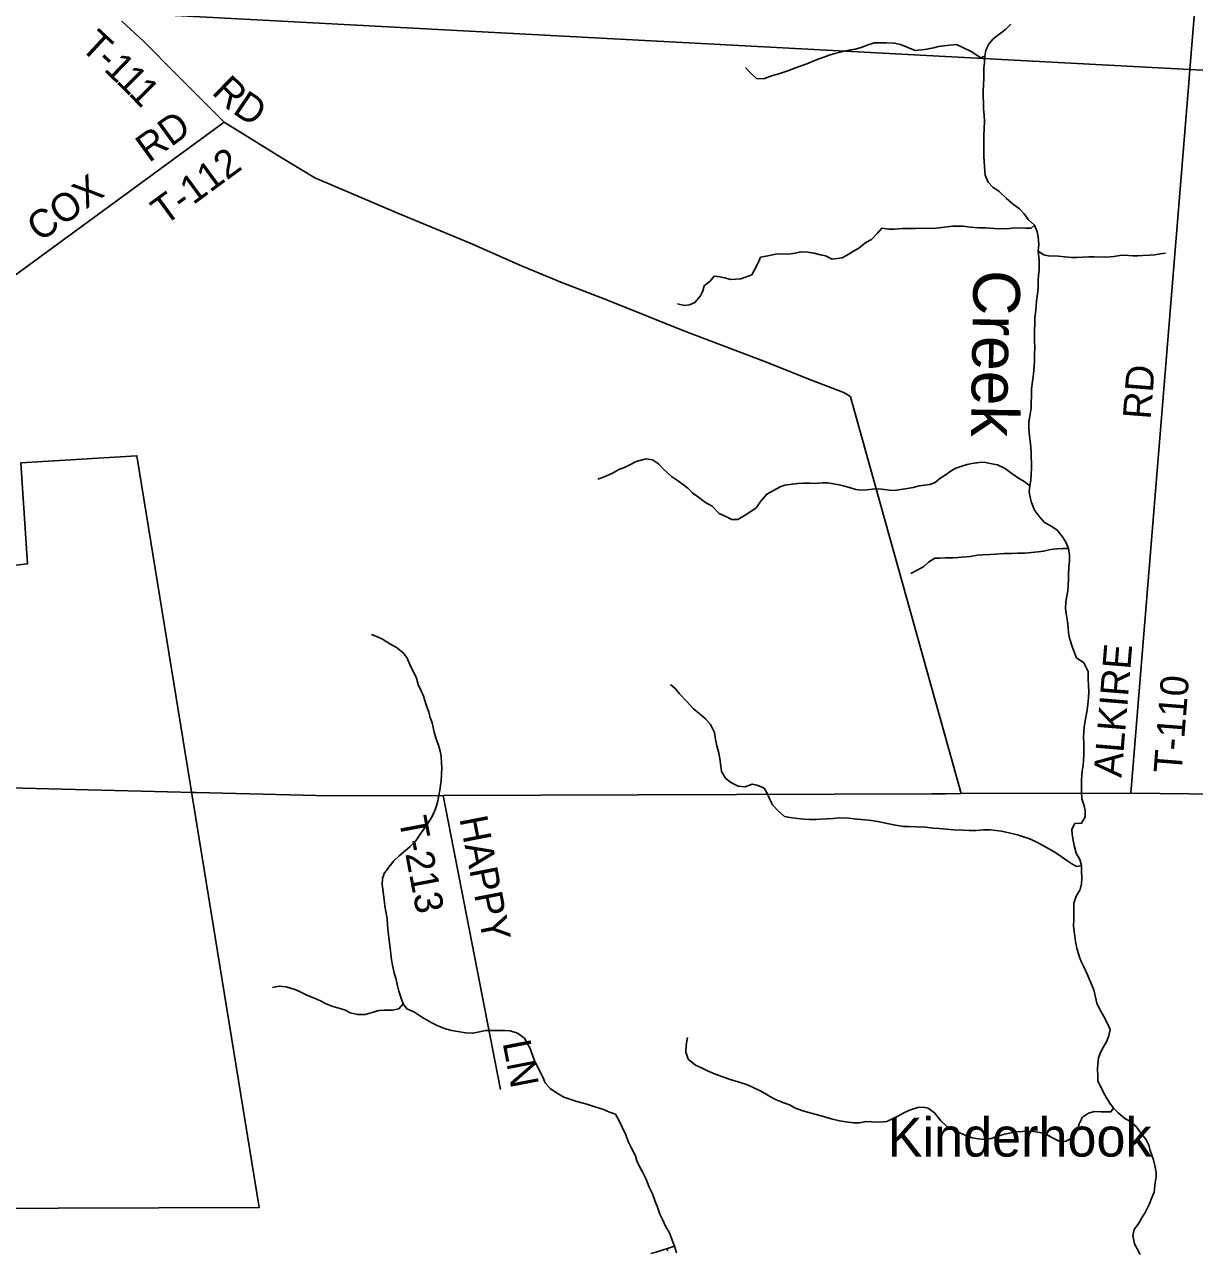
# Model space of a CAD drawing. Extents: x 1643459 to 2064572, y 425441 to 780708.
# Drawn here: x 1795345 to 1807853, y 573105 to 586239 of the extents above; entities that cross this region are included whole.
import ezdxf

# ---------------------------------------------------------------- set-up
doc = ezdxf.new("R2010")
doc.units = 0
for name, color, linetype in [('GM_X_City_Street', 7, 'Continuous'), ('GM_X_Interchange_Ramps', 7, 'Continuous'), ('GM_X_Major_River', 7, 'Continuous'), ('GM_X_Major_River_Text', 7, 'Continuous'), ('GM_X_Rail_Line_Text', 7, 'Continuous'), ('GM_X_Township_ROW', 7, 'Continuous'), ('GM_X_US_Route', 7, 'Continuous'), ('RD_X_Wall', 7, 'Continuous')]:
    doc.layers.add(name, color=color, linetype=linetype)

msp = doc.modelspace()

# ---------------------------------------------------------------- linework, layer by layer
at = {"layer": 'GM_X_City_Street'}
for points in [[(1826247, 584864), (1815752, 585365), (1810346, 585624), (1807802, 585759), (1796284, 586370), (1794642, 586457), (1794061, 586488), (1794168, 588257), (1794631, 595981), (1795084, 602890), (1800646, 605476), (1807239, 608541), (1807901, 608849), (1810366, 609995), (1808540, 616123), (1806771, 622059), (1811221, 621850), (1814649, 621689), (1819572, 621457), (1824722, 621285)], [(1796284, 586370), (1807802, 585759), (1810346, 585624)]]:
    msp.add_lwpolyline(points, dxfattribs=at)
at = {"layer": 'GM_X_Major_River_Text'}
for points in [[(1807791, 585617), (1807791, 585617), (1807802, 585759), (1808205, 590701)], [(1796386, 586275), (1796625, 586054), (1796961, 585710), (1797480, 585194), (1798089, 584818), (1798447, 584601), (1799319, 584229), (1800109, 583900), (1800658, 583659), (1801077, 583485), (1801559, 583297), (1802394, 582964), (1803249, 582640), (1803760, 582434), (1804094, 582305), (1804136, 582287), (1804176, 582258), (1805360, 578012)], [(1807172, 578017), (1807791, 585617)], [(1797480, 585194), (1795041, 583413)], [(1799821, 577994), (1800432, 574849)]]:
    msp.add_lwpolyline(points, dxfattribs=at)
at = {"layer": 'GM_X_Rail_Line_Text'}
msp.add_lwpolyline([(1792093, 580095), (1795375, 580469), (1795306, 581550), (1796546, 581627), (1797852, 573585), (1792480, 573568)], dxfattribs=at)
at = {"layer": 'GM_X_US_Route'}
for points in [[(1806475, 579990), (1806477, 580064), (1806490, 580124), (1806500, 580182), (1806502, 580238), (1806507, 580311), (1806507, 580365), (1806510, 580431), (1806516, 580507), (1806518, 580561), (1806505, 580635), (1806477, 580702), (1806442, 580760), (1806386, 580831), (1806329, 580869), (1806251, 580914), (1806199, 580968), (1806144, 581045), (1806110, 581127), (1806095, 581183), (1806087, 581242), (1806094, 581304), (1806104, 581366), (1806111, 581492), (1806109, 581548), (1806108, 581612), (1806106, 581666), (1806102, 581717), (1806095, 581783), (1806091, 581841), (1806083, 581919), (1806082, 581989), (1806094, 582051), (1806107, 582134), (1806107, 582192), (1806112, 582266), (1806110, 582342), (1806121, 582422), (1806127, 582472), (1806140, 582574), (1806144, 582653), (1806144, 582719), (1806145, 582785), (1806143, 582857), (1806144, 582973), (1806148, 583033), (1806147, 583104), (1806153, 583156), (1806162, 583228), (1806164, 583282), (1806174, 583360), (1806181, 583422), (1806181, 583504), (1806184, 583554), (1806192, 583614), (1806194, 583669), (1806191, 583719), (1806183, 583815), (1806190, 583887), (1806182, 583969), (1806171, 584022), (1806143, 584092), (1806076, 584154), (1806034, 584213), (1805982, 584269), (1805919, 584314), (1805843, 584377), (1805766, 584453), (1805698, 584498), (1805647, 584554), (1805617, 584629), (1805608, 584721), (1805606, 584775), (1805602, 584829), (1805601, 584897), (1805601, 584970), (1805600, 585050), (1805606, 585130), (1805607, 585198), (1805603, 585272), (1805598, 585338), (1805596, 585405), (1805594, 585463), (1805595, 585525), (1805597, 585595), (1805600, 585661), (1805600, 585711), (1805602, 585775), (1805609, 585834), (1805613, 585900), (1805623, 585966), (1805654, 586030), (1805698, 586084), (1805762, 586131), (1805833, 586187), (1805889, 586243)], [(1805613, 585900), (1805569, 585882), (1805464, 585949), (1805382, 585991), (1805310, 586024), (1805238, 586020), (1805174, 586013), (1805118, 586003), (1805062, 585990), (1804992, 585974), (1804938, 585968), (1804866, 585963), (1804787, 585995), (1804711, 586026), (1804647, 586041), (1804561, 586043), (1804428, 586044), (1804366, 586022), (1804291, 585995), (1804225, 585977), (1804157, 585964), (1804095, 585950), (1804009, 585929), (1803947, 585911), (1803891, 585891), (1803819, 585866), (1803727, 585826), (1803659, 585801), (1803599, 585781), (1803507, 585744), (1803409, 585712), (1803331, 585691), (1803257, 585661), (1803175, 585658), (1803109, 585718), (1803054, 585781)], [(1806143, 584092), (1806107, 584060), (1806047, 584062), (1805927, 584063), (1805875, 584058), (1805801, 584054), (1805711, 584059), (1805620, 584065), (1805548, 584066), (1805458, 584072), (1805376, 584083), (1805270, 584084), (1805206, 584076), (1805126, 584065), (1805058, 584059), (1804946, 584060), (1804871, 584058), (1804797, 584059), (1804731, 584057), (1804645, 584052), (1804585, 584052), (1804511, 584061), (1804463, 584009), (1804400, 583941), (1804338, 583906), (1804264, 583848), (1804208, 583814), (1804152, 583779), (1804088, 583745), (1804032, 583735), (1803980, 583730), (1803908, 583764), (1803856, 583777), (1803786, 583793), (1803719, 583804), (1803641, 583808), (1803583, 583793), (1803511, 583783), (1803443, 583785), (1803379, 583784), (1803273, 583763), (1803213, 583749), (1803187, 583691), (1803154, 583623), (1803120, 583563), (1803002, 583518), (1802894, 583511), (1802842, 583527), (1802782, 583541), (1802718, 583548), (1802676, 583494), (1802612, 583444), (1802597, 583390), (1802571, 583336), (1802513, 583267), (1802455, 583241), (1802401, 583233), (1802327, 583250)], [(1806183, 583815), (1806241, 583774), (1806293, 583766), (1806399, 583761), (1806466, 583753), (1806540, 583748), (1806592, 583746), (1806656, 583752), (1806724, 583755), (1806782, 583753), (1806916, 583752), (1806990, 583757), (1807054, 583769), (1807106, 583771), (1807194, 583766), (1807246, 583766), (1807297, 583769), (1807371, 583771), (1807429, 583774), (1807485, 583786), (1807543, 583794)], [(1806094, 581304), (1806034, 581350), (1805970, 581385), (1805901, 581437), (1805823, 581492), (1805747, 581529), (1805668, 581545), (1805604, 581558), (1805550, 581554), (1805474, 581544), (1805422, 581533), (1805366, 581515), (1805302, 581494), (1805252, 581464), (1805186, 581420), (1805131, 581384), (1805081, 581341), (1805023, 581319), (1804967, 581313), (1804911, 581304), (1804847, 581286), (1804783, 581275), (1804715, 581267), (1804643, 581255), (1804591, 581258), (1804539, 581266), (1804476, 581273), (1804408, 581269), (1804348, 581263), (1804288, 581260), (1804234, 581264), (1804174, 581285), (1804110, 581301), (1804056, 581314), (1803995, 581326), (1803929, 581336), (1803877, 581337), (1803797, 581331), (1803741, 581332), (1803669, 581334), (1803611, 581331), (1803553, 581321), (1803475, 581311), (1803425, 581294), (1803353, 581254), (1803281, 581217), (1803218, 581141), (1803168, 581069), (1803110, 581029), (1803050, 580990), (1802972, 580944), (1802908, 580946), (1802850, 580973), (1802770, 581008), (1802695, 581086), (1802627, 581127), (1802568, 581171), (1802486, 581230), (1802436, 581280), (1802377, 581325), (1802325, 581363), (1802263, 581404), (1802178, 581483), (1802122, 581541), (1802057, 581584), (1801991, 581594), (1801937, 581579), (1801885, 581565), (1801815, 581529), (1801761, 581500), (1801707, 581482), (1801631, 581442), (1801536, 581399), (1801474, 581377)], [(1806505, 580635), (1806445, 580634), (1806383, 580632), (1806317, 580623), (1806239, 580605), (1806181, 580597), (1806111, 580590), (1806039, 580586), (1805961, 580585), (1805897, 580581), (1805817, 580580), (1805724, 580573), (1805668, 580571), (1805586, 580567), (1805532, 580562), (1805454, 580548), (1805324, 580539), (1805270, 580536), (1805192, 580536), (1805128, 580532), (1805076, 580531), (1805008, 580487), (1804958, 580443), (1804888, 580402), (1804819, 580368)], [(1807257, 573419), (1807289, 573475), (1807325, 573533), (1807370, 573619), (1807392, 573683), (1807421, 573749), (1807433, 573853), (1807444, 573909), (1807442, 573963), (1807428, 574035), (1807415, 574094), (1807381, 574194), (1807366, 574252), (1807334, 574315), (1807281, 574379), (1807231, 574450), (1807162, 574510), (1807108, 574539), (1807036, 574597), (1806989, 574648), (1806947, 574702), (1806916, 574753), (1806878, 574821), (1806852, 574875), (1806821, 574938), (1806819, 574996), (1806818, 575062), (1806820, 575120), (1806828, 575186), (1806849, 575244), (1806879, 575304), (1806911, 575358), (1806936, 575422), (1806952, 575490), (1806921, 575559), (1806883, 575629), (1806838, 575709), (1806810, 575770), (1806796, 575834), (1806777, 575912), (1806738, 576007), (1806708, 576075), (1806671, 576158), (1806643, 576216), (1806619, 576274), (1806594, 576361), (1806582, 576429), (1806575, 576487), (1806567, 576537), (1806560, 576599), (1806564, 576670), (1806565, 576788), (1806565, 576840), (1806587, 576914), (1806630, 576986), (1806644, 577046), (1806649, 577104), (1806647, 577188), (1806647, 577242), (1806626, 577307), (1806588, 577377), (1806567, 577459), (1806557, 577512), (1806544, 577578), (1806542, 577634), (1806574, 577692), (1806646, 577698), (1806685, 577763), (1806683, 577832), (1806673, 577882), (1806648, 577958), (1806646, 578036), (1806647, 578106), (1806645, 578161), (1806654, 578255), (1806662, 578313), (1806668, 578371), (1806669, 578423), (1806671, 578477), (1806670, 578551), (1806666, 578614), (1806670, 578674), (1806673, 578726), (1806693, 578832), (1806706, 578904), (1806712, 578966), (1806721, 579038), (1806725, 579104), (1806719, 579164), (1806718, 579249), (1806716, 579319), (1806671, 579411), (1806591, 579466), (1806570, 579520), (1806544, 579587), (1806517, 579677), (1806505, 579731), (1806504, 579785), (1806496, 579854), (1806483, 579938), (1806475, 579990)], [(1799805, 578287), (1799802, 578345), (1799800, 578410), (1799788, 578466), (1799771, 578532), (1799747, 578596), (1799726, 578671), (1799704, 578769), (1799681, 578825), (1799667, 578884), (1799638, 578962), (1799610, 579056), (1799587, 579113), (1799555, 579179), (1799534, 579247), (1799510, 579300), (1799482, 579356), (1799453, 579418), (1799431, 579469), (1799390, 579521), (1799322, 579576), (1799250, 579616), (1799171, 579665), (1799117, 579689), (1799055, 579714)], [(1806647, 577242), (1806593, 577233), (1806542, 577263), (1806490, 577298), (1806414, 577352), (1806353, 577389), (1806245, 577452), (1806166, 577494), (1806082, 577531), (1806026, 577551), (1805972, 577568), (1805915, 577582), (1805791, 577611), (1805669, 577624), (1805597, 577626), (1805523, 577619), (1805445, 577617), (1805380, 577620), (1805282, 577625), (1805122, 577638), (1805058, 577642), (1804982, 577653), (1804882, 577657), (1804799, 577660), (1804743, 577660), (1804657, 577675), (1804569, 577694), (1804467, 577714), (1804372, 577729), (1804248, 577740), (1804154, 577751), (1804058, 577753), (1803992, 577748), (1803924, 577744), (1803856, 577739), (1803804, 577737), (1803738, 577737), (1803681, 577740), (1803609, 577748), (1803529, 577757), (1803469, 577769), (1803401, 577828), (1803340, 577894), (1803312, 577949), (1803287, 578009), (1803251, 578071), (1803178, 578104), (1803126, 578114), (1803048, 578085), (1802976, 578093), (1802896, 578132), (1802840, 578178), (1802797, 578249), (1802789, 578307), (1802778, 578389), (1802768, 578446), (1802747, 578522), (1802731, 578590), (1802720, 578666), (1802680, 578753), (1802627, 578811), (1802549, 578876), (1802498, 578919), (1802422, 579001), (1802347, 579080), (1802303, 579134), (1802250, 579181)], [(1802317, 573102), (1802294, 573172), (1802258, 573263), (1802241, 573313), (1802203, 573379), (1802166, 573456), (1802138, 573514), (1802109, 573598), (1802087, 573649), (1802060, 573733), (1802024, 573804), (1801989, 573896), (1801955, 573958), (1801926, 574011), (1801892, 574085), (1801876, 574139), (1801833, 574220), (1801798, 574290), (1801772, 574363), (1801735, 574445), (1801703, 574513), (1801662, 574582), (1801598, 574606), (1801534, 574633), (1801442, 574662), (1801357, 574692), (1801305, 574705), (1801249, 574719), (1801111, 574766), (1801022, 574819), (1800964, 574857), (1800911, 574920), (1800889, 574972), (1800857, 575032), (1800832, 575087), (1800798, 575153), (1800781, 575205), (1800751, 575286), (1800720, 575344), (1800690, 575396), (1800614, 575449), (1800537, 575476), (1800479, 575480), (1800403, 575477), (1800331, 575479), (1800275, 575479), (1800193, 575460), (1800135, 575450), (1800061, 575453), (1799979, 575467), (1799912, 575480), (1799846, 575498), (1799764, 575527), (1799700, 575562), (1799601, 575618), (1799513, 575673), (1799434, 575712), (1799394, 575764), (1799370, 575824), (1799345, 575899), (1799331, 575955), (1799314, 576039), (1799296, 576092), (1799277, 576196), (1799265, 576260), (1799256, 576336), (1799244, 576441), (1799233, 576533), (1799227, 576605), (1799222, 576673), (1799206, 576752), (1799197, 576808), (1799189, 576880), (1799184, 576930), (1799176, 576989), (1799170, 577039), (1799171, 577105), (1799191, 577157), (1799241, 577225), (1799294, 577292), (1799350, 577348), (1799464, 577444), (1799529, 577509), (1799567, 577567), (1799621, 577643), (1799660, 577701), (1799702, 577767), (1799737, 577849), (1799759, 577917), (1799775, 577991), (1799786, 578049), (1799792, 578099), (1799798, 578151), (1799803, 578219), (1799805, 578287)], [(1799394, 575764), (1799348, 575712), (1799280, 575697), (1799194, 575697), (1799132, 575694), (1799060, 575670), (1798988, 575651), (1798908, 575649), (1798828, 575666), (1798776, 575696), (1798705, 575717), (1798631, 575739), (1798563, 575768), (1798511, 575796), (1798458, 575819), (1798362, 575855), (1798286, 575896), (1798229, 575922), (1798139, 575947), (1798067, 575952), (1797997, 575940)], [(1806989, 574648), (1806959, 574610), (1806857, 574609), (1806785, 574611), (1806721, 574596), (1806657, 574550), (1806620, 574480), (1806602, 574418), (1806559, 574342), (1806481, 574296), (1806421, 574289), (1806320, 574338), (1806262, 574372), (1806198, 574389), (1806136, 574397), (1806070, 574402), (1806011, 574400), (1805947, 574394), (1805875, 574381), (1805823, 574371), (1805731, 574340), (1805681, 574324), (1805613, 574312), (1805545, 574319), (1805481, 574329), (1805409, 574356), (1805345, 574384), (1805280, 574425), (1805206, 574450), (1805140, 574512), (1805073, 574599), (1805007, 574647), (1804952, 574660), (1804896, 574656), (1804818, 574631), (1804753, 574603), (1804687, 574567), (1804633, 574538), (1804563, 574506), (1804487, 574498), (1804401, 574503), (1804343, 574506), (1804271, 574492), (1804206, 574490), (1804128, 574501), (1804058, 574513), (1803970, 574532), (1803912, 574551), (1803771, 574590), (1803717, 574604), (1803655, 574622), (1803589, 574649), (1803522, 574684), (1803462, 574706), (1803374, 574741), (1803320, 574769), (1803257, 574808), (1803195, 574842), (1803143, 574865), (1803074, 574897), (1802984, 574926), (1802888, 574956), (1802801, 574985), (1802721, 575016), (1802645, 575048), (1802581, 575081), (1802520, 575109), (1802440, 575172), (1802415, 575248), (1802419, 575321), (1802434, 575403)], [(1807271, 573082), (1807239, 573143), (1807211, 573197), (1807194, 573285), (1807210, 573349), (1807257, 573419)], [(1802294, 573172), (1802098, 573107), (1802040, 573094)], [(1802213, 573127), (1802228, 573135)]]:
    msp.add_lwpolyline(points, dxfattribs=at)
at = {"layer": 'RD_X_Wall'}
for points in [[(1805046, 578011), (1805200, 578011), (1805360, 578012), (1807172, 578017), (1808110, 578008), (1810084, 578044), (1811860, 578033), (1818856, 578689), (1821751, 578929), (1826832, 580172)], [(1795119, 578076), (1795183, 578074), (1797155, 578026), (1797180, 578025)], [(1797180, 578025), (1798604, 577990), (1799821, 577994), (1805046, 578011)]]:
    msp.add_lwpolyline(points, dxfattribs=at)

# ---------------------------------------------------------------- texts
at = {"layer": 'GM_X_Interchange_Ramps'}
msp.add_text('Creek', height=500, rotation=269.1152, dxfattribs=at).set_placement((1805491, 583616))
at = {"layer": 'GM_X_Major_River'}
for s, rotation, p in [('T', 317.2371, (1795930, 585988)), ('-', 316.7832, (1796094, 585836)), ('1', 316.023, (1796183, 585753)), ('1', 315.1546, (1796315, 585625)), ('R', 315.9053, (1797337, 585506)), ('1', 314.6541, (1796446, 585495)), ('D', 326.1642, (1797558, 585298)), ('RD', 35.883, (1796676, 584755)), ('T-112', 36.2539, (1796842, 584081)), ('COX', 35.7643, (1795510, 583906)), ('RD', 85.5622, (1807385, 582010)), ('ALKIRE', 85.3138, (1807072, 578179)), ('T-110', 85.4938, (1807714, 578221)), ('T-213', 280.7585, (1799344, 577742)), ('HAPPY', 280.981, (1799993, 577747)), ('LN', 280.9052, (1800455, 575349))]:
    msp.add_text(s, height=300, rotation=rotation, dxfattribs=at).set_placement(p)
at = {"layer": 'GM_X_Township_ROW'}
msp.add_text('Kinderhook', height=417, rotation=0, dxfattribs=at).set_placement((1804573, 574130))

doc.saveas('drawing.dxf')
